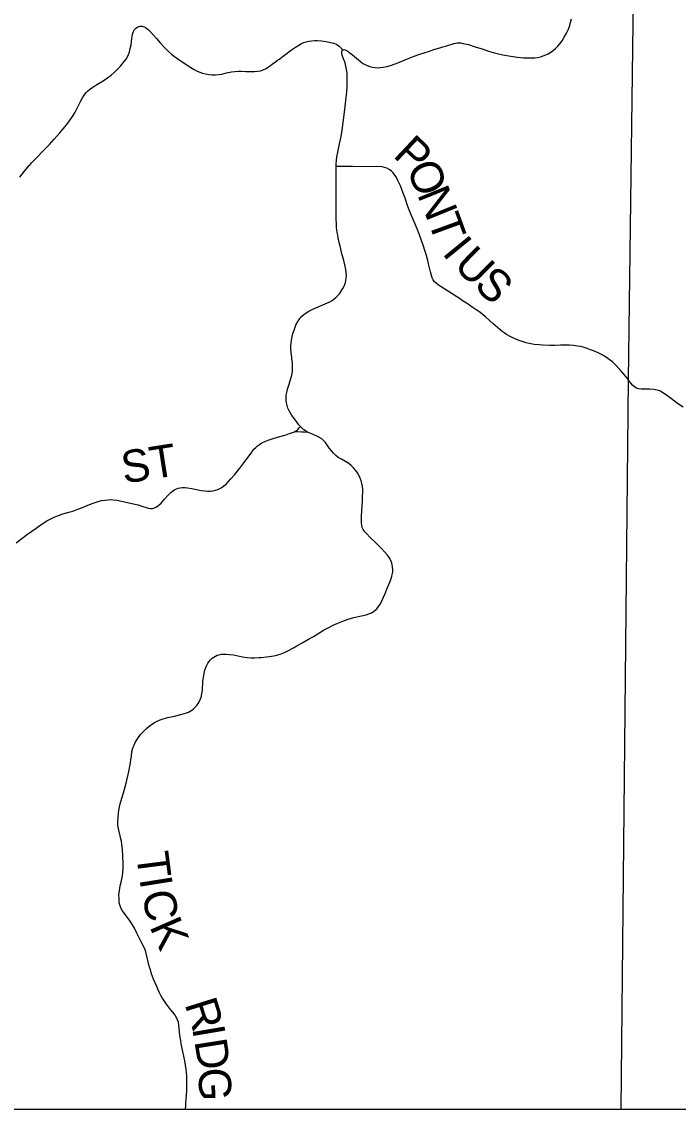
# Model space of a CAD drawing. Extents: x -10.5 to 40.6, y -3.2 to 22.
# Drawn here: x -7.268 to -6.111, y 14.1 to 16.014 of the extents above; entities that cross this region are included whole.
import ezdxf

# ---------------------------------------------------------------- set-up
doc = ezdxf.new("R2010")
doc.units = 0
for name, color, linetype in [('GM_X_Township_Road', 7, 'Continuous'), ('GM_X_Township_Road_Text', 7, 'Continuous'), ('GM_X_Township_Text', 7, 'Continuous'), ('SH_Text', 7, 'Continuous')]:
    doc.layers.add(name, color=color, linetype=linetype)

msp = doc.modelspace()

# ---------------------------------------------------------------- linework, layer by layer
at = {"layer": 'GM_X_Township_Road'}
for points in [[(-7.271, 15.7406), (-7.2625, 15.7511), (-7.2543, 15.7611), (-7.2535, 15.762), (-7.2516, 15.7644), (-7.2504, 15.7658), (-7.2496, 15.7667), (-7.2471, 15.7695), (-7.2441, 15.7726), (-7.2274, 15.7894), (-7.2188, 15.7983), (-7.2104, 15.8075), (-7.2051, 15.8135), (-7.2003, 15.8191), (-7.1943, 15.8261), (-7.1881, 15.8336), (-7.1833, 15.8399), (-7.1782, 15.8474), (-7.1742, 15.8542), (-7.1687, 15.8644), (-7.1633, 15.8753), (-7.1604, 15.8807), (-7.1576, 15.8853), (-7.1565, 15.8871), (-7.1542, 15.8899), (-7.1515, 15.8925), (-7.1482, 15.8953), (-7.1426, 15.8992), (-7.1352, 15.9038), (-7.1241, 15.9106), (-7.1163, 15.9157), (-7.1103, 15.9202), (-7.1046, 15.925), (-7.0992, 15.9302), (-7.0937, 15.9361), (-7.087, 15.9442), (-7.0837, 15.9488), (-7.0815, 15.9525), (-7.0794, 15.957), (-7.0777, 15.9617), (-7.0763, 15.9671), (-7.075, 15.9738), (-7.0734, 15.9848), (-7.0722, 15.9922), (-7.0713, 15.9958), (-7.0701, 15.9987), (-7.0687, 16.0008), (-7.0671, 16.0026), (-7.0651, 16.0041), (-7.0629, 16.0053), (-7.0606, 16.0061), (-7.0587, 16.0065), (-7.0563, 16.0065), (-7.0544, 16.0062), (-7.0521, 16.0055), (-7.0493, 16.0041), (-7.047, 16.0025), (-7.0441, 16.0003), (-7.0408, 15.9969), (-7.0302, 15.9852), (-7.0237, 15.9775), (-7.0175, 15.9705), (-7.0102, 15.9633), (-7.0038, 15.9575), (-6.9984, 15.9534), (-6.9902, 15.9476), (-6.9854, 15.9442), (-6.9777, 15.9392), (-6.9695, 15.934), (-6.9638, 15.9303), (-6.9588, 15.9277), (-6.9537, 15.9254), (-6.949, 15.9238), (-6.9436, 15.9225), (-6.9381, 15.9216), (-6.9325, 15.9212), (-6.9263, 15.9212), (-6.9207, 15.9216), (-6.9152, 15.9224), (-6.9067, 15.9242), (-6.8981, 15.926), (-6.892, 15.9269), (-6.8858, 15.9274), (-6.8809, 15.9274), (-6.8728, 15.9271), (-6.8635, 15.9266), (-6.8573, 15.9267), (-6.8517, 15.9272), (-6.8469, 15.9282), (-6.8423, 15.9299), (-6.8371, 15.9324), (-6.8331, 15.9349), (-6.8292, 15.9373), (-6.8262, 15.9395), (-6.8207, 15.9436), (-6.8168, 15.9466), (-6.8137, 15.9486), (-6.8093, 15.952), (-6.8048, 15.9554), (-6.7924, 15.9647), (-6.7853, 15.9697), (-6.7795, 15.9733), (-6.7746, 15.976), (-6.7706, 15.9777), (-6.7665, 15.9791), (-6.7617, 15.9803), (-6.7569, 15.9811), (-6.7513, 15.9815), (-6.7464, 15.9815), (-6.7396, 15.9808), (-6.7316, 15.9797), (-6.7237, 15.9781), (-6.7177, 15.9765), (-6.7126, 15.9741), (-6.7086, 15.9714), (-6.7042, 15.9676), (-6.7014, 15.9651)], [(-6.7014, 15.9651), (-6.7002, 15.9654), (-6.6966, 15.9644), (-6.6932, 15.9625), (-6.689, 15.9593), (-6.6851, 15.9564), (-6.6709, 15.9445), (-6.6665, 15.9411), (-6.6628, 15.9389), (-6.6594, 15.9373), (-6.6547, 15.9357), (-6.6499, 15.9345), (-6.645, 15.9338), (-6.64, 15.9335), (-6.6363, 15.9337), (-6.6307, 15.9344), (-6.6247, 15.9357), (-6.6181, 15.9375), (-6.6099, 15.9404), (-6.5965, 15.9455), (-6.581, 15.9518), (-6.5682, 15.9566), (-6.557, 15.9604), (-6.5493, 15.9628), (-6.5434, 15.9647), (-6.5379, 15.9665), (-6.5313, 15.9686), (-6.526, 15.9701), (-6.521, 15.9717), (-6.5158, 15.9734), (-6.5113, 15.9746), (-6.5066, 15.9759), (-6.5037, 15.9765), (-6.5006, 15.9771), (-6.4975, 15.9773), (-6.4944, 15.9771), (-6.4902, 15.9764), (-6.4841, 15.9749), (-6.4808, 15.9741), (-6.477, 15.9729), (-6.4723, 15.9714), (-6.4669, 15.9698), (-6.4569, 15.9665), (-6.4456, 15.9629), (-6.4373, 15.9603), (-6.4302, 15.9584), (-6.4204, 15.9563), (-6.4064, 15.9539), (-6.3941, 15.9521), (-6.3836, 15.9511), (-6.3756, 15.9506), (-6.3687, 15.9506), (-6.3638, 15.951), (-6.3589, 15.9517), (-6.354, 15.9527), (-6.3492, 15.9542), (-6.3446, 15.9559), (-6.3401, 15.9581), (-6.3354, 15.961), (-6.3313, 15.9639), (-6.3276, 15.9672), (-6.3241, 15.9707), (-6.32, 15.9754), (-6.316, 15.9809), (-6.312, 15.9872), (-6.3081, 15.9943), (-6.3048, 16.0014), (-6.3024, 16.0077), (-6.3008, 16.0129), (-6.2993, 16.0193)], [(-6.7137, 15.7597), (-6.7136, 15.7641), (-6.7132, 15.7703), (-6.7124, 15.7765), (-6.711, 15.785), (-6.708, 15.7996), (-6.7052, 15.8124), (-6.7033, 15.8234), (-6.6985, 15.8597), (-6.6966, 15.8758), (-6.6951, 15.8912), (-6.6945, 15.8986), (-6.6941, 15.9079), (-6.6941, 15.9158), (-6.6946, 15.9238), (-6.6955, 15.9305), (-6.6966, 15.9365), (-6.6981, 15.9418), (-6.7008, 15.9493), (-6.703, 15.9557), (-6.7038, 15.9584), (-6.704, 15.9602), (-6.7036, 15.9624), (-6.7031, 15.9635), (-6.7024, 15.9645), (-6.7014, 15.9651)], [(-6.7767, 15.302), (-6.7793, 15.3051), (-6.7824, 15.3091), (-6.7874, 15.3156), (-6.7916, 15.3212), (-6.7942, 15.3253), (-6.7966, 15.3296), (-6.7987, 15.3341), (-6.8003, 15.3388), (-6.8014, 15.3436), (-6.8019, 15.3479), (-6.802, 15.3522), (-6.8017, 15.3571), (-6.8009, 15.362), (-6.7995, 15.3674), (-6.7967, 15.3762), (-6.7941, 15.3845), (-6.792, 15.3923), (-6.7912, 15.3959), (-6.7908, 15.399), (-6.7905, 15.4021), (-6.7905, 15.4083), (-6.7909, 15.4131), (-6.7913, 15.4171), (-6.7916, 15.421), (-6.7919, 15.4237), (-6.7924, 15.4274), (-6.7929, 15.4329), (-6.7933, 15.4383), (-6.7935, 15.4437), (-6.7932, 15.4494), (-6.7924, 15.4541), (-6.7913, 15.4603), (-6.7898, 15.4657), (-6.788, 15.4715), (-6.7861, 15.4768), (-6.784, 15.482), (-6.782, 15.4858), (-6.7797, 15.4895), (-6.777, 15.4929), (-6.774, 15.496), (-6.7707, 15.4989), (-6.7667, 15.5018), (-6.762, 15.5047), (-6.7548, 15.5084), (-6.7457, 15.5124), (-6.7331, 15.5177), (-6.7263, 15.5208), (-6.7219, 15.5232), (-6.7183, 15.5256), (-6.7145, 15.5287), (-6.7114, 15.5318), (-6.7081, 15.5355), (-6.7048, 15.54), (-6.7019, 15.5447), (-6.6997, 15.5492), (-6.6979, 15.5538), (-6.6966, 15.5586), (-6.696, 15.5629), (-6.6958, 15.5679), (-6.6959, 15.5728), (-6.6966, 15.5784), (-6.6984, 15.5865), (-6.7004, 15.594), (-6.7026, 15.6024), (-6.7035, 15.606), (-6.7049, 15.6114), (-6.706, 15.6169), (-6.7066, 15.6193), (-6.7076, 15.6235), (-6.71, 15.6339), (-6.7109, 15.6387), (-6.7117, 15.6436), (-6.7124, 15.6479), (-6.7129, 15.6518), (-6.7133, 15.6563), (-6.7134, 15.6601), (-6.7137, 15.666), (-6.7139, 15.6708), (-6.7139, 15.6746), (-6.7139, 15.6801), (-6.7137, 15.6838), (-6.7138, 15.6868), (-6.7136, 15.6899), (-6.7136, 15.6948), (-6.7135, 15.6991), (-6.7136, 15.7066), (-6.7136, 15.7129), (-6.7136, 15.7203), (-6.7138, 15.7271), (-6.714, 15.7363), (-6.7139, 15.7461), (-6.7138, 15.7559), (-6.7137, 15.7597)], [(-6.1984, 15.383), (-6.1991, 15.3838), (-6.2037, 15.3898), (-6.2144, 15.4025), (-6.2223, 15.4112), (-6.2268, 15.4155), (-6.2327, 15.42), (-6.2374, 15.4231), (-6.2453, 15.4279), (-6.2524, 15.4316), (-6.2603, 15.435), (-6.2657, 15.4371), (-6.2717, 15.4394), (-6.2767, 15.4408), (-6.2826, 15.4425), (-6.2888, 15.4436), (-6.2955, 15.4444), (-6.3029, 15.4448), (-6.3184, 15.4449), (-6.3289, 15.4446), (-6.3374, 15.4445), (-6.3503, 15.4451), (-6.3563, 15.4455), (-6.3652, 15.4463), (-6.3737, 15.4478), (-6.3791, 15.4492), (-6.3897, 15.4527), (-6.3971, 15.4557), (-6.4061, 15.4598), (-6.4138, 15.4639), (-6.4179, 15.4666), (-6.4214, 15.4691), (-6.4253, 15.4724), (-6.4378, 15.4835), (-6.4504, 15.4946), (-6.461, 15.5031), (-6.4671, 15.5075), (-6.4743, 15.5122), (-6.4792, 15.5155), (-6.4843, 15.5189), (-6.4901, 15.5227), (-6.4963, 15.527), (-6.5014, 15.5302), (-6.5179, 15.5407), (-6.5335, 15.5506), (-6.5379, 15.554), (-6.5407, 15.5566), (-6.5432, 15.56), (-6.5446, 15.5635), (-6.5459, 15.5676), (-6.5474, 15.5742), (-6.5503, 15.5859), (-6.5521, 15.5939), (-6.5548, 15.6027), (-6.5575, 15.6119), (-6.5602, 15.6193), (-6.5672, 15.6392), (-6.5711, 15.6497), (-6.5766, 15.6621), (-6.5813, 15.6734), (-6.5858, 15.6846), (-6.5887, 15.6928), (-6.5925, 15.7039), (-6.5956, 15.7127), (-6.6006, 15.7254), (-6.6049, 15.7348), (-6.6083, 15.7416), (-6.6104, 15.7446), (-6.6134, 15.7485), (-6.6165, 15.7516), (-6.6205, 15.7546), (-6.6243, 15.7565), (-6.6284, 15.758), (-6.6326, 15.7589), (-6.6401, 15.7594), (-6.6612, 15.7593), (-6.6848, 15.7594), (-6.7078, 15.7596), (-6.7137, 15.7597)], [(-6.1026, 15.3359), (-6.1124, 15.3424), (-6.1234, 15.3506), (-6.1337, 15.3584), (-6.1399, 15.3626), (-6.1437, 15.3645), (-6.1484, 15.3661), (-6.1545, 15.3673), (-6.1613, 15.3679), (-6.1687, 15.3679), (-6.1767, 15.3676), (-6.181, 15.368), (-6.1845, 15.3691), (-6.1877, 15.371), (-6.191, 15.3738), (-6.1946, 15.378), (-6.1984, 15.383)], [(-6.7864, 15.2932), (-6.7846, 15.2942), (-6.7826, 15.2957), (-6.7813, 15.2969), (-6.7791, 15.2993), (-6.7767, 15.302)], [(-6.7641, 15.292), (-6.7675, 15.294), (-6.7705, 15.2961), (-6.7733, 15.2985), (-6.7767, 15.302)], [(-7.2774, 15.0973), (-7.2575, 15.1122), (-7.2424, 15.1232), (-7.2332, 15.1295), (-7.2231, 15.1357), (-7.2161, 15.1395), (-7.2094, 15.1427), (-7.2025, 15.1455), (-7.1954, 15.148), (-7.1847, 15.1511), (-7.1775, 15.1531), (-7.1746, 15.1541), (-7.1688, 15.1562), (-7.1607, 15.1594), (-7.1481, 15.1647), (-7.14, 15.1677), (-7.1329, 15.1699), (-7.127, 15.1714), (-7.1209, 15.1724), (-7.1155, 15.173), (-7.11, 15.1731), (-7.1064, 15.1729), (-7.1003, 15.1721), (-7.0918, 15.1704), (-7.0683, 15.1652), (-7.0623, 15.1638), (-7.0558, 15.1618), (-7.0482, 15.1593), (-7.0447, 15.1584), (-7.041, 15.1578), (-7.0374, 15.1577), (-7.0339, 15.1587), (-7.0311, 15.1599), (-7.0285, 15.1615), (-7.0256, 15.1638), (-7.0221, 15.1672), (-7.0158, 15.174), (-7.0095, 15.1808), (-7.0047, 15.1856), (-7.0013, 15.1884), (-6.9982, 15.1905), (-6.9949, 15.1921), (-6.9919, 15.1931), (-6.9883, 15.1939), (-6.9846, 15.1944), (-6.9803, 15.1944), (-6.9754, 15.1939), (-6.9681, 15.1928), (-6.9513, 15.1894), (-6.9452, 15.1885), (-6.9403, 15.1882), (-6.9354, 15.1883), (-6.9305, 15.1889), (-6.9262, 15.1899), (-6.9221, 15.1912), (-6.9187, 15.1927), (-6.9149, 15.1948), (-6.9113, 15.1973), (-6.9075, 15.2005), (-6.9031, 15.2049), (-6.899, 15.2095), (-6.8923, 15.2176), (-6.8834, 15.2287), (-6.8762, 15.238), (-6.874, 15.241), (-6.8624, 15.257), (-6.8585, 15.2618), (-6.8555, 15.2649), (-6.8522, 15.2677), (-6.8487, 15.2703), (-6.8445, 15.2729), (-6.8395, 15.2754), (-6.8338, 15.2778), (-6.8262, 15.2804), (-6.8173, 15.2831), (-6.8042, 15.2868), (-6.8018, 15.2875), (-6.796, 15.2894), (-6.7908, 15.2913), (-6.7873, 15.2927), (-6.7864, 15.2932)], [(-6.8461, 14.8954), (-6.8409, 14.8957), (-6.832, 14.8969), (-6.8236, 14.8982), (-6.8164, 14.9), (-6.8105, 14.9018), (-6.8047, 14.9041), (-6.7986, 14.907), (-6.7888, 14.9123), (-6.7828, 14.9157), (-6.7737, 14.921), (-6.7623, 14.9273), (-6.7537, 14.9322), (-6.7489, 14.9351), (-6.7358, 14.9431), (-6.7267, 14.9483), (-6.719, 14.9523), (-6.7111, 14.9559), (-6.7019, 14.9595), (-6.6925, 14.9629), (-6.6825, 14.9658), (-6.672, 14.9682), (-6.6612, 14.9706), (-6.6563, 14.972), (-6.6518, 14.974), (-6.6485, 14.9757), (-6.6455, 14.9779), (-6.6424, 14.981), (-6.6393, 14.9848), (-6.6361, 14.9894), (-6.634, 14.9932), (-6.6305, 15.0012), (-6.6277, 15.008), (-6.6231, 15.0182), (-6.6193, 15.0278), (-6.6169, 15.0343), (-6.6155, 15.0386), (-6.6145, 15.043), (-6.6141, 15.0464), (-6.6141, 15.0502), (-6.6145, 15.0545), (-6.6153, 15.0588), (-6.6165, 15.0629), (-6.6182, 15.0669), (-6.6205, 15.0713), (-6.6234, 15.0755), (-6.6279, 15.0807), (-6.6344, 15.0875), (-6.6441, 15.0971), (-6.6542, 15.1072), (-6.6599, 15.1129), (-6.6633, 15.1166), (-6.666, 15.1206), (-6.6677, 15.1241), (-6.6686, 15.1281), (-6.6689, 15.1318), (-6.6693, 15.1373), (-6.6691, 15.1449), (-6.6681, 15.1624), (-6.6676, 15.1706), (-6.6674, 15.1737), (-6.6671, 15.1793), (-6.6669, 15.1853), (-6.6668, 15.191), (-6.6674, 15.1965), (-6.6683, 15.2013), (-6.6696, 15.2061), (-6.6713, 15.2107), (-6.6734, 15.2152), (-6.6762, 15.2201), (-6.6794, 15.2246), (-6.683, 15.2289), (-6.6873, 15.2333), (-6.6912, 15.2365), (-6.6975, 15.2404), (-6.7045, 15.2442), (-6.71, 15.2476), (-6.7143, 15.251), (-6.7182, 15.255), (-6.7215, 15.2584), (-6.7252, 15.2632), (-6.729, 15.2687), (-6.7328, 15.274), (-6.7358, 15.2774), (-6.7391, 15.28), (-6.743, 15.2824), (-6.7477, 15.2846), (-6.7586, 15.2894), (-6.7641, 15.292)], [(-6.7864, 15.2932), (-6.7818, 15.2929), (-6.7746, 15.2925), (-6.7696, 15.2923), (-6.7641, 15.292)], [(-7.0016, 14.2707), (-7.0022, 14.2715), (-7.0072, 14.2779), (-7.0127, 14.2852), (-7.0173, 14.2918), (-7.0202, 14.2964), (-7.0224, 14.3002), (-7.0254, 14.3062), (-7.0303, 14.317), (-7.0353, 14.329), (-7.0387, 14.3383), (-7.0416, 14.3471), (-7.043, 14.3519), (-7.045, 14.3596), (-7.0477, 14.3716), (-7.0491, 14.377), (-7.0503, 14.3805), (-7.0519, 14.3845), (-7.0558, 14.3923), (-7.0605, 14.4017), (-7.0647, 14.4101), (-7.0691, 14.419), (-7.0725, 14.4249), (-7.0766, 14.4311), (-7.0833, 14.4401), (-7.0887, 14.4476), (-7.0917, 14.4524), (-7.0936, 14.4562), (-7.0949, 14.4597), (-7.0957, 14.4633), (-7.0962, 14.467), (-7.0962, 14.4713), (-7.0963, 14.4772), (-7.0954, 14.4851), (-7.094, 14.4932), (-7.0927, 14.4995), (-7.0913, 14.5057), (-7.0903, 14.511), (-7.0896, 14.5166), (-7.0891, 14.5233), (-7.0891, 14.5329), (-7.0892, 14.5454), (-7.0901, 14.5575), (-7.0911, 14.5659), (-7.092, 14.5721), (-7.0928, 14.5758), (-7.0944, 14.5816), (-7.0967, 14.5915), (-7.0976, 14.5964), (-7.0981, 14.6007), (-7.0982, 14.6063), (-7.0978, 14.6137), (-7.097, 14.6218), (-7.0957, 14.6297), (-7.094, 14.6376), (-7.0911, 14.6477), (-7.0883, 14.6572), (-7.0846, 14.6698), (-7.0829, 14.6764), (-7.0791, 14.6946), (-7.0762, 14.7099), (-7.0752, 14.7154), (-7.0744, 14.7209), (-7.0734, 14.7296), (-7.0725, 14.7338), (-7.0713, 14.7373), (-7.0697, 14.7407), (-7.0675, 14.7458), (-7.0637, 14.7521), (-7.0581, 14.7596), (-7.0525, 14.7658), (-7.0471, 14.7708), (-7.0425, 14.7749), (-7.0381, 14.7781), (-7.0335, 14.781), (-7.029, 14.7832), (-7.0239, 14.7855), (-7.0182, 14.7873), (-7.0103, 14.7894), (-6.9983, 14.7919), (-6.9875, 14.7947), (-6.9792, 14.7971), (-6.974, 14.799), (-6.9707, 14.8007), (-6.968, 14.8023), (-6.9651, 14.8046), (-6.9619, 14.8076), (-6.9591, 14.8109), (-6.9566, 14.8145), (-6.9545, 14.8183), (-6.9527, 14.8222), (-6.9512, 14.827), (-6.9501, 14.8318), (-6.9493, 14.8373), (-6.9483, 14.8534), (-6.9476, 14.8602), (-6.9464, 14.867), (-6.945, 14.873), (-6.9434, 14.8777), (-6.9417, 14.8817), (-6.9396, 14.8855), (-6.9374, 14.8885), (-6.935, 14.8913), (-6.9322, 14.8939), (-6.9292, 14.8961), (-6.9265, 14.8976), (-6.9231, 14.8991), (-6.9196, 14.9002), (-6.9159, 14.901), (-6.9122, 14.9013), (-6.9072, 14.9013), (-6.9017, 14.9008), (-6.8943, 14.8997), (-6.8785, 14.8962), (-6.8698, 14.8952), (-6.8635, 14.8948), (-6.8575, 14.8948), (-6.8502, 14.8952), (-6.8461, 14.8954)], [(-6.9793, 14.1), (-6.9792, 14.1018), (-6.9788, 14.1049), (-6.9786, 14.1078), (-6.9784, 14.1121), (-6.978, 14.1171), (-6.9776, 14.1245), (-6.977, 14.1319), (-6.9768, 14.1368), (-6.9767, 14.1536), (-6.9768, 14.1592), (-6.9772, 14.1641), (-6.9778, 14.1697), (-6.9789, 14.1777), (-6.9803, 14.185), (-6.9838, 14.2014), (-6.9866, 14.2154), (-6.9875, 14.2209), (-6.9888, 14.2301), (-6.9906, 14.248), (-6.9917, 14.2535), (-6.9931, 14.2576), (-6.9949, 14.2615), (-6.9959, 14.2631), (-6.9976, 14.2657), (-7.0016, 14.2707)]]:
    msp.add_lwpolyline(points, dxfattribs=at)
at = {"layer": 'GM_X_Township_Text'}
msp.add_lwpolyline([(-6.1874, 16.891), (-6.1985, 16.7494), (-6.1956, 16.4198), (-6.1883, 16.2366), (-6.1993, 15.3843), (-6.2122, 14.1), (-3.7445, 14.1), (-3.7445, 16.8499)], dxfattribs=at)
at = {"layer": 'SH_Text'}
msp.add_lwpolyline([(-10.5445, 16.0741), (-10.5445, 14.1), (-6.2122, 14.1)], dxfattribs=at)

# ---------------------------------------------------------------- texts
at = {"layer": 'GM_X_Township_Road_Text'}
for s, height, rotation, p in [('P', 0.0568, 316.7978, (-6.6153, 15.7778)), ('O', 0.0568, 292.7992, (-6.5909, 15.7567)), ('N', 0.0568, 292.0429, (-6.5716, 15.7107)), ('T', 0.0568, 289.9882, (-6.553, 15.6649)), ('I', 0.0568, 309.2078, (-6.5283, 15.6069)), ('U', 0.0568, 315.5616, (-6.5089, 15.5838)), ('S', 0.0568, 315.9637, (-6.4729, 15.5485)), ('ST', 0.05682, 8.8802, (-7.0877, 15.2013)), ('T', 0.0568, 277.2664, (-7.0661, 14.55)), ('I', 0.0568, 279.0725, (-7.0604, 14.5059)), ('C', 0.0568, 281.3138, (-7.0563, 14.4805)), ('K', 0.0568, 293.5754, (-7.0432, 14.422)), ('R', 0.0568, 287.4043, (-6.981, 14.2855)), ('I', 0.0568, 279.6946, (-6.9675, 14.2429)), ('D', 0.0568, 278.9024, (-6.9636, 14.2201)), ('G', 0.0568, 271.2059, (-6.9561, 14.1727))]:
    msp.add_text(s, height=height, rotation=rotation, dxfattribs=at).set_placement(p)

doc.saveas('drawing.dxf')
